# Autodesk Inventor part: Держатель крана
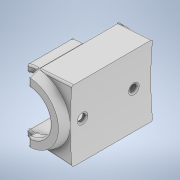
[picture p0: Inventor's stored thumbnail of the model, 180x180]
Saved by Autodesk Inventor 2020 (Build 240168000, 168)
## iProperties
Created: 2024-03
Part Number: Держатель крана
Material: Типовые
Document SubType Name: Modeling
Designer: Pavel
Density: 1 g/cm^3
Appearance: По умолчанию
Author: Pavel
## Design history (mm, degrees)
sketch "Эскиз1"
  geometry: L1 (0, 0)-(8.25, 0); L2 (8.25, 0)-(8.25, 5); L3 (8.25, 5)-(13.25, 5); L4 (13.25, 5)-(13.25, 25); L5 (13.25, 25)-(13.6, 25); L6 (13.6, 25)-(13.6, 37); L7 (13.6, 37)-(14.75, 37); L8 (14.75, 37)-(14.75, 51); L9 (14.75, 51)-(12, 51); L10 (12, 51)-(12, 56); L11 (12, 56)-(0, 56); L12 (12, 56)-(17, 56); L13 (17, 56)-(17, 51); L14 (17, 51)-(19.75, 51); L15 (19.75, 51)-(19.75, 37); L16 (13.6, 37)-(14.75, 37); L17 (19.75, 37)-(18.677, 37); L18 (18.677, 37)-(18.677, 25); L19 (18.25, 25)-(18.25, 5); L20 (18.677, 25)-(18.25, 25); L21 (13.25, 0)-(18.25, 5); L22 (13.25, 0)-(8.25, 0); L23 (0, 56)-(0, 66); L24 (18.677, 37)-(18.677, 51); L25 (18.677, 25)-(18.677, 5.427); L26 (18.25, 5)-(18.677, 5.427); L27 (18.677, 51)-(17, 56)
  constraints: 54 end point, 13 perpendicular, 4 horizontal, 2 collinear, 2 point on line, 2 vertical, 1 parallel
  dimensions: "d0" = 8.25 distance of L1.start L1.end; "d2" = 5 distance of L2.end L3.end; "d3" = 20 distance of L3.end L4.end; "d4" = 0.35 distance of L4.end L5.end; "d5" = 12 distance of L5.end L6.end; "d6" = 1.15 distance of L7.end L6.end; "d7" = 14 distance of L7.end L8.end; "d8" = 2.75 distance of L8.end L9.end; "d9" = 5 distance of L9.end L10.end; "d10" = 12 distance of L10.end L11.end; "d11" = 5 distance of L8.end L14.end; "d12" = 5 distance of L4.end L19.start
revolve "Вращение1" sketch "Эскиз1" stored, may be unused: angle "d14" = 90 deg
sketch "Эскиз2"
  geometry: L1 (0, -26.926)-(0, 26.926); C1 r 8.25 at (0, 0) reference; A1 r 26.926 centre (0, 0) between (0, -26.926) and (0, 26.926); 3 further points
  constraints: 2 end point, 2 point on circle, 1 centre point, 1 coincident, 1 vertical
extrude "Выдавливание1" cut sketch "Эскиз2" stored distance "d15" = 10; taper "d16" = 0 deg
sketch "Эскиз5"
  geometry: L1 (6, 20)-(20, 20); L2 (20, 20)-(20, -19); L3 (20, -19)-(6, -19); L4 (6, -19)-(6, 20); 1 further point
  constraints: 8 end point, 2 parallel, 1 horizontal, 1 perpendicular
extrude "Выдавливание4" cut sketch "Эскиз5" stored distance "d22" = 50; taper "d23" = 0 deg
sketch "Эскиз6"
  geometry: L1 (0, 24)-(0, -24); A1 r 24 centre (0, 0) between (0, 24) and (0, -24); 1 further point
  constraints: 2 end point, 2 point on circle, 1 centre point, 1 coincident, 1 vertical
extrude "Выдавливание5" cut sketch "Эскиз6" stored distance "d24" = 30; taper "d25" = 0 deg
fillet "Сопряжение2" dims "d26" = 1
node "РабПлоскость1"
sketch "Эскиз7"
  geometry: L1 (0, -8.25)-(25, -8.25); L2 (25, -8.25)-(15, -8.25); C1 r 2 at (15, -8.25)
  constraints: 4 end point, 1 centre point, 1 coincident, 1 horizontal, 1 point on line
  dimensions: "d28" = 4 diameter of C1
extrude "Выдавливание6" cut sketch "Эскиз7" distance "d29" = 30; taper "d31" = 0 deg; dims "d30" = 15, "d32" = 0
sketch "Эскиз8"
  geometry: C1 r 5.5 at (15, -8.25); 1 further point
  constraints: 1 centre point
  dimensions: "d33" = 11 diameter of C1
extrude "Выдавливание7" cut sketch "Эскиз8" distance "d34" = 5; taper "d35" = 0 deg; dims "d36" = 2, "d37" = 0
node "РабПлоскость2"
sketch "Эскиз9"
  geometry: L1 (51, 3.75)-(51, -20.25) reference; L2 (51, -8.25)-(44, -8.25); L3 (37, 5.35)-(37, -21.85) reference; C1 r 2 at (44, -8.25); 3 further points
  constraints: 2 end point, 1 centre point, 1 coincident, 1 midpoint, 1 perpendicular
  dimensions: "d39" = 7 distance of L2.start L2.end; "d40" = 4 diameter of C1
extrude "Выдавливание8" cut sketch "Эскиз9" distance "d41" = 5; taper "d43" = 0 deg; dims "d42" = 10, "d44" = 0
sketch "Эскиз10"
  geometry: C1 r 5.5 at (44, -8.25); 1 further point
  constraints: 1 centre point
  dimensions: "d45" = 11 diameter of C1
extrude "Выдавливание9" cut sketch "Эскиз10" distance "d46" = 5; taper "d48" = 0 deg; dims "d47" = 2, "d49" = 0
sketch "Эскиз11"
  geometry: L1 (-18.677, 0)-(-213.677, 0); L2 (0, -13.6)-(0, -18.677) reference; L3 (0, -18.677)-(-19.705, -20); L4 (0, 18.677)-(-19.705, 20); A1 r 18.677 centre (0, 0) between (0, 18.677) and (0, -18.677) reference; A2 r 195 centre (-213.677, 0) between (-19.705, -20) and (-19.705, 20); A3 r 18.677 centre (0, 0) between (6, 17.687) and (0, 18.677) reference; A4 r 18.677 centre (0, 0) between (0, 18.677) and (0, -18.677); 2 further points
  constraints: 6 end point, 5 point on circle, 2 centre point, 1 coincident, 1 concentric, 1 horizontal
  dimensions: "d50" = 195 distance of L1.start L1.end; "d51" = 390 diameter of A2
extrude "Выдавливание10" join sketch "Эскиз11" stored distance "d52" = 5; taper "d53" = 0 deg
sketch "Эскиз12"
  geometry: L1 (0, -13.6)-(0, -18.677) reference; L2 (-19.705, -20)-(0, -18.677) reference; L3 (0, -18.677)-(-19.705, -20); L4 (-19.705, 20)-(0, 18.677); L5 (0, 18.677)-(-19.705, 20) reference; A1 r 18.677 centre (0, 0) between (0, 18.677) and (-18.677, 0) reference; A2 r 18.677 centre (0, 0) between (-18.677, 0) and (0, -18.677) reference; A3 r 18.677 centre (0, 0) between (0, 18.677) and (0, -18.677); A4 r 18.677 centre (0, 0) between (6, 17.687) and (0, 18.677) reference; A5 r 195 centre (-213.677, 0) between (-19.705, -20) and (-19.705, 20); 3 further points
  constraints: 4 end point, 4 point on circle, 2 centre point, 1 collinear, 1 concentric
extrude "Выдавливание11" cut sketch "Эскиз12" distance "d54" = 5.427; taper "d55" = 0 deg
sketch "Эскиз13"
  geometry: L1 (13.206, 13.206)-(28.076, 0.209) reference; L2 (-0.209, -28.076)-(-13.206, -13.206) reference; L3 (13.206, 13.206)-(12.021, 12.021) reference; L4 (28.076, 0.209)-(13.206, 13.206); L5 (-13.206, -13.206)-(-0.209, -28.076); A1 r 18.677 centre (0, 0) between (-13.206, -13.206) and (13.206, 13.206); A2 r 18.677 centre (0, 0) between (-13.206, -13.206) and (13.206, -13.206) reference; A3 r 195 centre (151.092, -151.092) between (28.076, 0.209) and (13.206, -13.206) reference; A4 r 195 centre (151.092, -151.092) between (28.076, 0.209) and (-0.209, -28.076); A5 r 18.677 centre (0, 0) between (-16.749, -8.264) and (-13.206, -13.206) reference; 3 further points
  constraints: 4 end point, 4 point on circle, 2 centre point, 1 concentric
extrude "Выдавливание12" cut sketch "Эскиз13" stored distance "d56" = 5.427; taper "d57" = 0 deg
sketch "Эскиз14"
  geometry: L1 (-2, 0)-(2, 0) reference; C1 r 2 at (0, 0); 1 further point
  constraints: 1 centre point, 1 midpoint
  dimensions: "d58" = 4 diameter of C1
extrude "Выдавливание13" cut sketch "Эскиз14" distance "d59" = 5.427; taper "d60" = 0 deg
sketch "Эскиз15"
  geometry: L1 (-2, 0)-(2, 0) reference; C1 r 2 at (0, 0); 1 further point
  constraints: 1 centre point, 1 midpoint
  dimensions: "d61" = 4 diameter of C1
extrude "Выдавливание14" cut sketch "Эскиз15" distance "d62" = 5.427; taper "d63" = 0 deg
fillet "Сопряжение3" dims "d64" = 1
fillet "Сопряжение4" dims "d65" = 1
fillet "Сопряжение5" dims "d66" = 1
fillet "Сопряжение6" dims "d67" = 1
node "Твердое тело1"
other parameters: "d27" = -13.25, "d38" = -14.75
